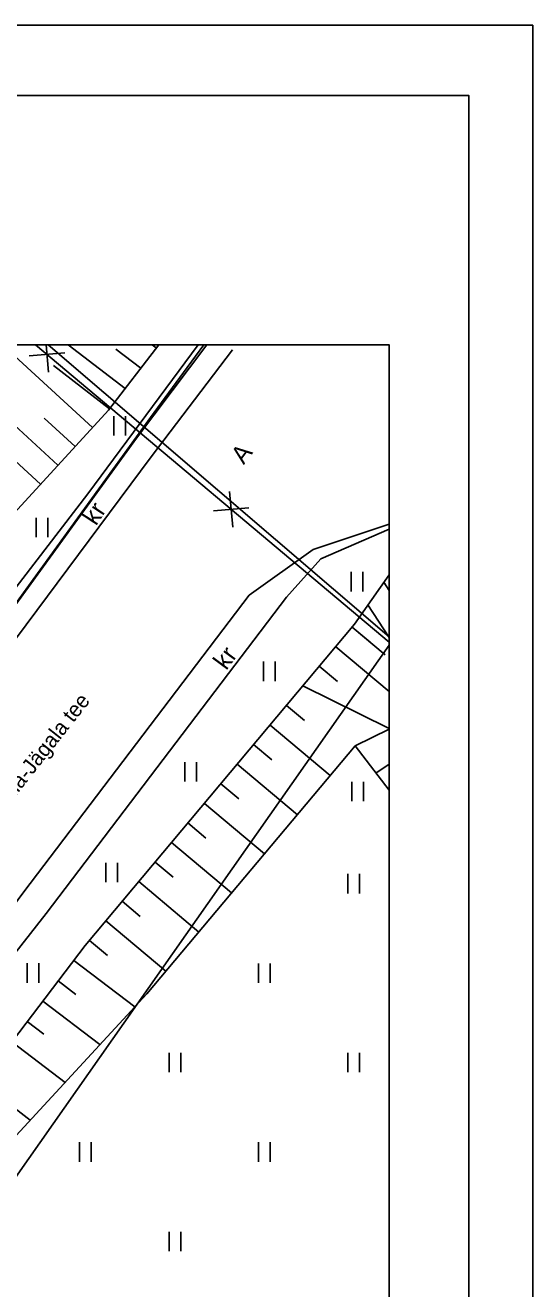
# Model space of a CAD drawing. Extents: x 565784.5 to 565837, y 6571808.3 to 6571882.6.
# Drawn here: x 565817.14 to 565837.01, y 6571833.15 to 6571882.59 of the extents above; entities that cross this region are included whole.
import ezdxf

# ---------------------------------------------------------------- set-up
doc = ezdxf.new("R2010")
doc.units = 0
for name, color, linetype in [('HALJASTUS', 7, 'Continuous'), ('PIIR', 7, 'Continuous'), ('RELJEEF', 7, 'Continuous'), ('SITRASS', 7, 'Continuous'), ('TEE', 7, 'Continuous'), ('TRUUP', 7, 'Continuous'), ('VORMISTUS', 7, 'Continuous')]:
    doc.layers.add(name, color=color, linetype=linetype)

msp = doc.modelspace()

# ---------------------------------------------------------------- linework, layer by layer
at = {"layer": 'HALJASTUS'}
for p, q in [((565820.607, 6571867.295), (565820.607, 6571866.533)), ((565821.062, 6571867.295), (565821.062, 6571866.533)), ((565817.572, 6571863.321), (565817.572, 6571862.56)), ((565818.027, 6571863.321), (565818.027, 6571862.56)), ((565829.901, 6571861.198), (565829.901, 6571860.437)), ((565830.357, 6571861.198), (565830.357, 6571860.437)), ((565826.469, 6571857.691), (565826.469, 6571856.93)), ((565826.924, 6571857.691), (565826.924, 6571856.93)), ((565823.385, 6571853.755), (565823.385, 6571852.994)), ((565823.84, 6571853.755), (565823.84, 6571852.994)), ((565829.929, 6571852.992), (565829.929, 6571852.231)), ((565830.384, 6571852.992), (565830.384, 6571852.231)), ((565820.301, 6571849.819), (565820.301, 6571849.058)), ((565820.756, 6571849.819), (565820.756, 6571849.058)), ((565829.772, 6571849.381), (565829.772, 6571848.619)), ((565830.228, 6571849.381), (565830.228, 6571848.619)), ((565817.218, 6571845.883), (565817.218, 6571845.122)), ((565817.673, 6571845.883), (565817.673, 6571845.122)), ((565826.272, 6571845.881), (565826.272, 6571845.119)), ((565826.728, 6571845.881), (565826.728, 6571845.119)), ((565822.772, 6571842.381), (565822.772, 6571841.619)), ((565823.228, 6571842.381), (565823.228, 6571841.619)), ((565829.772, 6571842.381), (565829.772, 6571841.619)), ((565830.228, 6571842.381), (565830.228, 6571841.619)), ((565819.272, 6571838.881), (565819.272, 6571838.119)), ((565819.728, 6571838.881), (565819.728, 6571838.119)), ((565826.272, 6571838.881), (565826.272, 6571838.119)), ((565826.728, 6571838.881), (565826.728, 6571838.119)), ((565822.772, 6571835.381), (565822.772, 6571834.619)), ((565823.228, 6571835.381), (565823.228, 6571834.619))]:
    msp.add_line(p, q, dxfattribs=at)
at = {"layer": 'PIIR'}
for points in [[(565831.382, 6571858.328), (565803.59, 6571818.77), (565802.507, 6571817.593)], [(565803.77, 6571817.593), (565803.59, 6571818.77), (565831.382, 6571858.328)]]:
    msp.add_lwpolyline(points, dxfattribs=at)
at = {"layer": 'RELJEEF'}
for p, q in [((565819.772, 6571866.846), (565816.402, 6571869.937)), ((565821.051, 6571868.38), (565818.82, 6571870.093)), ((565821.66, 6571869.174), (565820.69, 6571869.918)), ((565822.269, 6571869.967), (565822.105, 6571870.093)), ((565818.419, 6571865.372), (565813.704, 6571869.699)), ((565820.442, 6571867.587), (565818.244, 6571869.274)), ((565819.096, 6571866.109), (565817.883, 6571867.222)), ((565817.743, 6571864.635), (565816.249, 6571866.006)), ((565831.176, 6571860.795), (565831.382, 6571860.477)), ((565830.558, 6571859.908), (565831.382, 6571858.633)), ((565829.937, 6571859.039), (565831.224, 6571857.959)), ((565829.937, 6571859.039), (565830.645, 6571858.445)), ((565829.295, 6571858.272), (565831.382, 6571856.522)), ((565828.652, 6571857.506), (565829.359, 6571856.913)), ((565828.009, 6571856.74), (565831.382, 6571855.079)), ((565827.366, 6571855.974), (565828.074, 6571855.38)), ((565826.724, 6571855.208), (565829.083, 6571853.229)), ((565826.081, 6571854.442), (565826.788, 6571853.849)), ((565825.438, 6571853.676), (565827.795, 6571851.698)), ((565830.868, 6571853.33), (565831.382, 6571853.675)), ((565824.795, 6571852.91), (565825.502, 6571852.317)), ((565824.153, 6571852.144), (565826.508, 6571850.168)), ((565823.51, 6571851.378), (565824.216, 6571850.785)), ((565822.867, 6571850.612), (565825.22, 6571848.637)), ((565822.225, 6571849.845), (565822.93, 6571849.253)), ((565821.582, 6571849.079), (565823.933, 6571847.107)), ((565820.939, 6571848.313), (565821.644, 6571847.722)), ((565820.296, 6571847.547), (565822.646, 6571845.576)), ((565819.654, 6571846.781), (565820.358, 6571846.19)), ((565819.039, 6571845.993), (565821.427, 6571844.177)), ((565818.434, 6571845.197), (565819.127, 6571844.669)), ((565817.828, 6571844.401), (565820.064, 6571842.701)), ((565817.223, 6571843.604), (565817.871, 6571843.112)), ((565816.618, 6571842.808), (565818.701, 6571841.225)), ((565815.408, 6571841.216), (565817.338, 6571839.749))]:
    msp.add_line(p, q, dxfattribs=at)
for points in [[(565800.51, 6571847.744), (565800.538, 6571847.723), (565801.66, 6571847.165), (565807.743, 6571853.735), (565820.396, 6571867.526), (565822.365, 6571870.093)], [(565831.382, 6571861.091), (565830.033, 6571859.153), (565819.486, 6571846.581), (565806.328, 6571829.271), (565803.644, 6571823.76)], [(565831.382, 6571855.049), (565830.061, 6571854.393), (565831.382, 6571852.654)], [(565830.061, 6571854.393), (565821.897, 6571844.686), (565807.174, 6571828.74), (565803.644, 6571823.76)]]:
    msp.add_lwpolyline(points, dxfattribs=at)
at = {"layer": 'SITRASS'}
for p, q in [((565817.96, 6571870.093), (565818.054, 6571869.013)), ((565817.296, 6571869.65), (565818.691, 6571869.771)), ((565825.142, 6571864.347), (565825.262, 6571862.952)), ((565824.505, 6571863.589), (565825.899, 6571863.71))]:
    msp.add_line(p, q, dxfattribs=at)
for points in [[(565790.132, 6571827.785), (565795.262, 6571834.475), (565801.765, 6571842.375), (565808.482, 6571851.414), (565811.284, 6571854.993), (565814.22, 6571858.353), (565815.357, 6571859.794), (565816.36, 6571859.39), (565822.04, 6571867.24), (565823.485, 6571869.196), (565824.132, 6571870.093)], [(565823.913, 6571870.093), (565819.589, 6571864.258), (565813.931, 6571856.898), (565805.842, 6571846.363), (565798.797, 6571837.231), (565791.619, 6571827.726), (565790.132, 6571825.916)], [(565817.539, 6571870.093), (565831.382, 6571858.454)]]:
    msp.add_lwpolyline(points, dxfattribs=at)
at = {"layer": 'TEE'}
for points in [[(565790.132, 6571825.178), (565798.874, 6571835.854), (565810.584, 6571851.423), (565821.499, 6571866.441), (565824.25, 6571870.093)], [(565790.132, 6571823.893), (565799.254, 6571835.472), (565811.058, 6571850.919), (565822.074, 6571865.705), (565825.255, 6571869.896)], [(565831.382, 6571863.074), (565828.407, 6571862.073), (565825.907, 6571860.285), (565817.092, 6571848.675), (565804.137, 6571831.188), (565797.898, 6571823.166), (565798.048, 6571821.994), (565800.139, 6571818.615), (565800.327, 6571817.593)], [(565831.382, 6571862.872), (565828.71, 6571861.712), (565827.373, 6571860.217), (565817.957, 6571847.828), (565804.535, 6571830.717), (565801.583, 6571826.805), (565800.955, 6571825.15), (565801.025, 6571821.866), (565801.467, 6571818.976), (565801.839, 6571817.593)]]:
    msp.add_lwpolyline(points, dxfattribs=at)
at = {"layer": 'TRUUP'}
msp.add_line((565818.036, 6571870.093), (565831.382, 6571858.658), dxfattribs=at)
at = {"layer": 'VORMISTUS'}
for points in [[(565784.507, 6571882.593), (565837.007, 6571882.593), (565837.007, 6571808.343), (565784.507, 6571808.343)], [(565787.007, 6571811.093), (565834.507, 6571811.093), (565834.507, 6571879.843), (565787.007, 6571879.843)], [(565787.007, 6571879.843), (565834.507, 6571879.843), (565834.507, 6571811.093), (565787.007, 6571811.093)], [(565831.382, 6571817.593), (565790.132, 6571817.593), (565790.132, 6571870.093), (565831.382, 6571870.093)]]:
    msp.add_lwpolyline(points, close=True, dxfattribs=at)

# ---------------------------------------------------------------- texts
at = {"layer": 'PIIR'}
msp.add_text('11310 Aruvalla-Jägala tee', height=0.6, rotation=51.7649, dxfattribs=at).set_placement((565813.94, 6571848.826))
at = {"layer": 'TEE'}
for s, rotation, p in [('A', 52.5067, (565825.694, 6571865.374)), ('kr', 56.7555, (565819.912, 6571862.977)), ('kr', 53.5871, (565825.011, 6571857.321))]:
    msp.add_text(s, height=0.7, rotation=rotation, dxfattribs=at).set_placement(p)

doc.saveas('drawing.dxf')
